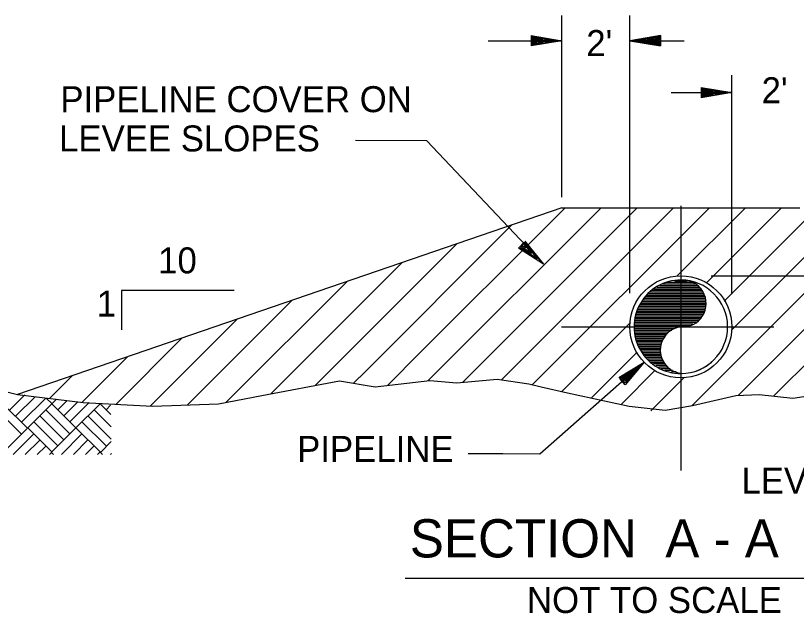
# Model space of a CAD drawing. Extents: x 2127959 to 2137375, y 2146193 to 2153470.
# Drawn here: x 2129309 to 2130299, y 2148422 to 2149179 of the extents above; entities that cross this region are included whole.
import ezdxf

# ---------------------------------------------------------------- set-up
doc = ezdxf.new("R2010")
doc.units = 0
for name, color, linetype in [('Level 1', 7, 'Continuous'), ('Level 3', 7, 'Continuous'), ('Level 5', 7, 'Continuous'), ('Level 50', 7, 'Continuous'), ('Level 63', 7, 'Continuous')]:
    doc.layers.add(name, color=color, linetype=linetype)

msp = doc.modelspace()

# ---------------------------------------------------------------- linework, layer by layer
at = {"layer": 'Level 1'}
for p, q in [((2129830.608, 2149020.936), (2129739.923, 2149021.327)), ((2129830.608, 2149020.936), (2129978.077, 2148864.503)), ((2130001.469, 2148936.091), (2129311.86, 2148699.457)), ((2130001.469, 2148936.091), (2129311.86, 2148699.457)), ((2130001.469, 2148936.091), (2129311.86, 2148699.457)), ((2130001.469, 2148936.091), (2130303.174, 2148936.091))]:
    msp.add_line(p, q, dxfattribs=at)
at = {"layer": 'Level 3'}
for p, q in [((2130001.469, 2148949.346), (2130001.469, 2149179.416)), ((2130087.67, 2148827.839), (2130087.67, 2149179.416)), ((2129908.122, 2149147.68), (2130001.469, 2149147.68)), ((2129962.715, 2149154.144), (2129962.715, 2149141.23)), ((2129962.715, 2149154.144), (2130001.469, 2149147.68)), ((2130001.469, 2149147.68), (2129962.715, 2149147.68)), ((2130001.469, 2149147.68), (2129962.715, 2149141.23)), ((2129963.277, 2149142.023), (2129995.687, 2149147.215)), ((2129963.449, 2149147.041), (2129963.277, 2149142.023)), ((2129963.484, 2149153.006), (2129963.424, 2149148.23)), ((2129963.424, 2149148.23), (2129995.739, 2149148.089)), ((2129964.239, 2149147.057), (2129964.231, 2149142.919)), ((2129964.231, 2149142.919), (2129988.269, 2149146.523)), ((2129995.687, 2149147.215), (2129964.239, 2149147.057)), ((2129964.298, 2149153.074), (2129964.282, 2149148.816)), ((2129964.282, 2149148.816), (2129988.487, 2149148.642)), ((2129995.739, 2149148.089), (2129964.298, 2149153.074)), ((2129988.269, 2149146.523), (2129965.053, 2149146.197)), ((2129965.053, 2149146.197), (2129965.127, 2149143.816)), ((2129965.127, 2149143.816), (2129977.802, 2149145.525)), ((2129988.487, 2149148.642), (2129965.141, 2149152.108)), ((2129965.141, 2149152.108), (2129965.141, 2149149.731)), ((2129965.141, 2149149.731), (2129977.627, 2149149.523)), ((2129977.802, 2149145.525), (2129966.028, 2149145.576)), ((2129966.028, 2149145.576), (2129966.043, 2149144.606)), ((2129977.627, 2149149.523), (2129966.07, 2149151.368)), ((2129966.07, 2149151.368), (2129966.096, 2149150.42)), ((2129966.096, 2149150.42), (2129969.76, 2149150.316)), ((2130126.42, 2149154.144), (2130087.67, 2149147.68)), ((2130087.67, 2149147.68), (2130156.332, 2149147.68)), ((2130087.67, 2149147.68), (2130126.42, 2149147.68)), ((2130087.67, 2149147.68), (2130126.42, 2149141.23)), ((2130125.617, 2149153.366), (2130094.223, 2149148.126)), ((2130094.223, 2149148.126), (2130125.008, 2149148.489)), ((2130125.792, 2149142.089), (2130094.32, 2149147.075)), ((2130094.32, 2149147.075), (2130124.949, 2149147.075)), ((2130124.949, 2149152.561), (2130100.454, 2149148.627)), ((2130100.454, 2149148.627), (2130124.084, 2149149.245)), ((2130125.045, 2149142.886), (2130100.607, 2149146.592)), ((2130100.607, 2149146.592), (2130124.181, 2149146.35)), ((2130124.012, 2149151.595), (2130109.712, 2149149.454)), ((2130109.712, 2149149.454), (2130123.298, 2149149.678)), ((2130124.161, 2149143.8), (2130109.897, 2149145.854)), ((2130109.897, 2149145.854), (2130123.397, 2149145.628)), ((2130123.355, 2149150.851), (2130119.26, 2149150.231)), ((2130123.298, 2149149.678), (2130123.355, 2149150.851)), ((2130123.397, 2149145.628), (2130123.571, 2149144.49)), ((2130124.084, 2149149.245), (2130124.012, 2149151.595)), ((2130124.181, 2149146.35), (2130124.161, 2149143.8)), ((2130125.008, 2149148.489), (2130124.949, 2149152.561)), ((2130124.949, 2149147.075), (2130125.045, 2149142.886)), ((2130125.68, 2149148.593), (2130125.617, 2149153.366)), ((2130125.728, 2149147.057), (2130125.792, 2149142.089)), ((2130126.42, 2149154.144), (2130126.42, 2149141.23)), ((2129966.043, 2149144.606), (2129969.63, 2149144.904)), ((2130123.571, 2149144.49), (2130119.245, 2149145.073)), ((2130216.974, 2148826.713), (2130216.974, 2149104.163)), ((2130178.219, 2149088.339), (2130178.219, 2149075.426)), ((2130178.219, 2149088.339), (2130216.974, 2149081.872)), ((2130178.985, 2149087.2), (2130178.927, 2149082.424)), ((2130179.803, 2149087.268), (2130179.784, 2149083.012)), ((2130211.241, 2149082.285), (2130179.803, 2149087.268)), ((2130203.988, 2149082.84), (2130180.645, 2149086.304)), ((2130180.645, 2149086.304), (2130180.645, 2149083.926)), ((2130139.865, 2149081.872), (2130216.974, 2149081.872)), ((2130216.974, 2149081.872), (2130178.219, 2149081.872)), ((2130216.974, 2149081.872), (2130178.219, 2149075.426)), ((2130178.783, 2149076.218), (2130211.189, 2149081.407)), ((2130178.952, 2149081.236), (2130178.783, 2149076.218)), ((2130178.927, 2149082.424), (2130211.241, 2149082.285)), ((2130179.741, 2149081.249), (2130179.731, 2149077.113)), ((2130179.731, 2149077.113), (2130203.773, 2149080.715)), ((2130211.189, 2149081.407), (2130179.741, 2149081.249)), ((2130179.784, 2149083.012), (2130203.988, 2149082.84)), ((2130203.773, 2149080.715), (2130180.556, 2149080.389)), ((2130180.556, 2149080.389), (2130180.63, 2149078.01)), ((2130180.63, 2149078.01), (2130193.304, 2149079.717)), ((2130180.645, 2149083.926), (2130193.128, 2149083.718)), ((2130193.304, 2149079.717), (2130181.528, 2149079.768)), ((2130181.528, 2149079.768), (2130181.548, 2149078.806)), ((2130181.548, 2149078.806), (2130185.129, 2149079.097)), ((2130193.128, 2149083.718), (2130181.574, 2149085.561)), ((2130181.574, 2149085.561), (2130181.602, 2149084.614)), ((2130181.602, 2149084.614), (2130185.264, 2149084.511)), ((2130152.32, 2148938.452), (2130152.32, 2148603.239)), ((2130190.765, 2148849.885), (2130836.581, 2148849.885)), ((2130190.765, 2148849.885), (2130836.581, 2148849.885)), ((2130190.765, 2148849.885), (2130836.581, 2148849.885)), ((2130170.464, 2148839.161), (2130129.065, 2148839.161)), ((2130167.662, 2148841.178), (2130133.054, 2148841.178)), ((2130160.279, 2148843.198), (2130144.8, 2148843.198)), ((2129443.731, 2148831.229), (2129443.731, 2148781.284)), ((2129586.223, 2148831.229), (2129443.731, 2148831.229)), ((2130179.993, 2148829.057), (2130113.055, 2148829.057)), ((2130178.761, 2148831.075), (2130114.821, 2148831.075)), ((2130177.534, 2148833.097), (2130118.277, 2148833.097)), ((2130176.062, 2148835.12), (2130121.872, 2148835.12)), ((2130173.263, 2148837.14), (2130125.472, 2148837.14)), ((2130183.467, 2148818.955), (2130104.241, 2148818.955)), ((2130183.171, 2148820.976), (2130106.003, 2148820.976)), ((2130182.873, 2148822.995), (2130107.768, 2148822.995)), ((2130182.446, 2148825.016), (2130109.531, 2148825.016)), ((2130181.215, 2148827.035), (2130111.298, 2148827.035)), ((2130183.749, 2148810.876), (2130099.656, 2148810.872)), ((2130184.273, 2148812.897), (2130100.449, 2148812.897)), ((2130184.06, 2148814.914), (2130101.25, 2148814.914)), ((2130183.763, 2148816.934), (2130102.478, 2148816.934)), ((2130180.646, 2148800.773), (2130095.664, 2148800.773)), ((2130181.651, 2148802.794), (2130096.467, 2148802.794)), ((2130182.176, 2148804.814), (2130097.261, 2148804.814)), ((2130182.701, 2148806.835), (2130098.06, 2148806.835)), ((2130183.227, 2148808.853), (2130098.855, 2148808.853)), ((2130171.188, 2148790.672), (2130094.078, 2148790.672)), ((2130174.449, 2148792.69), (2130094.147, 2148792.688)), ((2130176, 2148794.711), (2130094.218, 2148794.711)), ((2130177.55, 2148796.734), (2130094.285, 2148796.734)), ((2130179.097, 2148798.752), (2130094.869, 2148798.752)), ((2130001.009, 2148785.236), (2130270.124, 2148785.236)), ((2130140.696, 2148780.569), (2130093.73, 2148780.569)), ((2130144.39, 2148782.587), (2130093.798, 2148782.587)), ((2130149.676, 2148784.609), (2130093.868, 2148784.609)), ((2130164.079, 2148786.631), (2130093.938, 2148786.631)), ((2130167.63, 2148788.651), (2130094.011, 2148788.651)), ((2130137.009, 2148778.549), (2130093.662, 2148778.549)), ((2130137.009, 2148778.549), (2130093.662, 2148778.549)), ((2130135.267, 2148776.529), (2130093.808, 2148776.529)), ((2130133.669, 2148774.511), (2130094.448, 2148774.511)), ((2130132.068, 2148772.49), (2130095.088, 2148772.49)), ((2130130.47, 2148770.471), (2130095.73, 2148770.471)), ((2130129.219, 2148768.447), (2130096.371, 2148768.447)), ((2130128.665, 2148766.428), (2130097.009, 2148766.428)), ((2130128.101, 2148764.404), (2130097.654, 2148764.404)), ((2130127.542, 2148762.387), (2130098.297, 2148762.387)), ((2130126.983, 2148760.366), (2130098.931, 2148760.366)), ((2130126.423, 2148758.348), (2130099.576, 2148758.348)), ((2130126.466, 2148756.326), (2130100.945, 2148756.326)), ((2130126.729, 2148754.305), (2130102.476, 2148754.305)), ((2130126.995, 2148752.285), (2130104.011, 2148752.285)), ((2130127.259, 2148750.263), (2130105.542, 2148750.263)), ((2130127.259, 2148750.263), (2130105.542, 2148750.263)), ((2130127.522, 2148748.244), (2130107.073, 2148748.245)), ((2130127.787, 2148746.223), (2130108.602, 2148746.223)), ((2130128.903, 2148744.203), (2130110.134, 2148744.203)), ((2130130.085, 2148742.186), (2130111.666, 2148742.186)), ((2130131.271, 2148740.163), (2130114.551, 2148740.163)), ((2130132.454, 2148738.145), (2130117.631, 2148738.145)), ((2130133.64, 2148736.124), (2130120.709, 2148736.124)), ((2130136.162, 2148734.1), (2130123.787, 2148734.1)), ((2130138.874, 2148732.084), (2130126.87, 2148732.084)), ((2130141.579, 2148730.06), (2130132.068, 2148730.06)), ((2130146.466, 2148728.04), (2130140.36, 2148728.04)), ((2130146.466, 2148728.04), (2130140.36, 2148728.04))]:
    msp.add_line(p, q, dxfattribs=at)
msp.add_lwpolyline([(2130105.729, 2148740.417), (2129973.646, 2148623.943), (2129926.672, 2148624.261), (2129882.878, 2148624.261)], dxfattribs=at)
msp.add_circle((2130152.321, 2148785.236), 64.651, dxfattribs=at)
for centre, radius, start, end in [((2130152.321, 2148785.236), 59.263, 89.972239, 270.065958), ((2130154.781, 2148814.702), 29.592, 265.228306, 93.676883), ((2130152.321, 2148785.236), 59.263, 270.065994, 89.972197), ((2130155.9, 2148755.7), 29.704, 96.821831, 267.669103), ((2130152.32, 2148785.238), 59.265, 270.001317, 317.112911)]:
    msp.add_arc(centre, radius, start, end, dxfattribs=at)
at = {"layer": 'Level 5'}
for p, q in [((2129801.831, 2148732.275), (2130005.64, 2148936.091)), ((2129832.32, 2148717.053), (2130051.356, 2148936.091)), ((2129875.769, 2148714.785), (2130097.071, 2148936.091)), ((2129924.935, 2148718.238), (2130142.782, 2148936.091)), ((2129964.13, 2148711.715), (2130188.501, 2148936.091)), ((2130147.792, 2148849.664), (2130234.214, 2148936.091)), ((2130184.514, 2148840.671), (2130279.93, 2148936.091)), ((2130207.28, 2148817.725), (2130319.902, 2148930.349)), ((2130216.843, 2148781.571), (2130353.941, 2148918.659)), ((2129745.443, 2148721.603), (2129938.221, 2148914.384)), ((2130166.072, 2148685.086), (2130387.975, 2148906.991)), ((2129689.057, 2148710.932), (2129868.63, 2148890.507)), ((2130225.007, 2148698.303), (2130422.013, 2148895.308)), ((2130270, 2148697.582), (2130456.049, 2148883.631)), ((2129632.671, 2148700.264), (2129799.032, 2148866.628)), ((2129576.284, 2148689.591), (2129729.434, 2148842.746)), ((2129527.382, 2148686.403), (2129659.839, 2148818.859)), ((2129480.285, 2148685.024), (2129590.244, 2148794.98)), ((2130001.418, 2148703.291), (2130088.682, 2148790.553)), ((2129436.685, 2148687.14), (2129520.645, 2148771.097)), ((2130038.949, 2148695.106), (2130096.919, 2148753.074)), ((2129393.228, 2148689.393), (2129451.05, 2148747.218)), ((2129780.594, 2148711.04), (2129801.625, 2148732.071)), ((2130076.54, 2148686.982), (2130119.681, 2148730.125)), ((2129352.545, 2148694.427), (2129381.455, 2148723.338)), ((2129737.527, 2148713.689), (2129745.301, 2148721.465)), ((2130114.13, 2148678.858), (2130156.822, 2148721.55)), ((2129256.196, 2148713.472), (2129311.86, 2148699.457)), ((2129621.533, 2148698.156), (2129719.629, 2148716.63)), ((2129719.629, 2148716.63), (2129764.825, 2148709.209)), ((2129764.825, 2148709.209), (2129834.102, 2148717.26)), ((2129834.102, 2148717.26), (2129868.641, 2148714.103)), ((2129868.641, 2148714.103), (2129919.763, 2148718.998)), ((2129919.763, 2148718.998), (2129959.628, 2148713.154)), ((2129959.628, 2148713.154), (2129975.225, 2148709.209)), ((2129975.225, 2148709.209), (2130008.78, 2148701.63)), ((2130008.78, 2148701.63), (2130086.936, 2148684.732)), ((2130294.175, 2148694.997), (2130348.058, 2148702.737)), ((2129302.25, 2148679.982), (2129321.236, 2148698.97)), ((2129309.884, 2148672.398), (2129334.186, 2148696.696)), ((2129311.86, 2148699.457), (2129395.148, 2148689.156)), ((2129347.779, 2148695.016), (2129317.499, 2148664.734)), ((2129348.287, 2148694.951), (2129355.6, 2148687.633)), ((2129355.468, 2148687.759), (2129361.082, 2148693.369)), ((2129363.07, 2148680.159), (2129374.608, 2148691.697)), ((2129566.464, 2148687.733), (2129621.533, 2148698.156)), ((2130167.267, 2148685.369), (2130221.936, 2148698.156)), ((2130221.936, 2148698.156), (2130251.347, 2148699.576)), ((2130251.347, 2148699.576), (2130294.175, 2148694.997)), ((2129293.99, 2148686.968), (2129324.34, 2148656.617)), ((2129324.993, 2148657.28), (2129355.472, 2148687.764)), ((2129385.945, 2148657.28), (2129355.468, 2148687.759)), ((2129388.351, 2148690.16), (2129370.71, 2148672.518)), ((2129402.644, 2148689.233), (2129378.322, 2148664.906)), ((2129385.945, 2148657.28), (2129416.422, 2148687.759)), ((2129395.148, 2148689.156), (2129482.978, 2148684.892)), ((2129416.422, 2148687.759), (2129430.029, 2148674.146)), ((2129424.054, 2148680.127), (2129429.792, 2148685.865)), ((2129482.978, 2148684.892), (2129566.464, 2148687.733)), ((2130086.936, 2148684.732), (2130132.33, 2148679.683)), ((2130132.33, 2148679.683), (2130167.267, 2148685.369)), ((2129286.39, 2148679.363), (2129316.738, 2148649.019)), ((2129340.229, 2148672.518), (2129370.71, 2148642.039)), ((2129347.818, 2148680.159), (2129378.323, 2148649.656)), ((2129430.666, 2148643.033), (2129401.18, 2148672.518)), ((2129408.821, 2148680.159), (2129430.349, 2148658.632)), ((2129363.07, 2148634.403), (2129332.569, 2148664.906)), ((2129424.072, 2148634.403), (2129393.57, 2148664.906)), ((2129293.858, 2148626.135), (2129324.331, 2148656.613)), ((2129355.468, 2148626.805), (2129324.993, 2148657.28)), ((2129355.468, 2148626.755), (2129385.945, 2148657.231)), ((2129385.945, 2148657.28), (2129416.422, 2148626.805)), ((2129306.513, 2148623.59), (2129331.958, 2148649.036)), ((2129339.572, 2148641.374), (2129321.785, 2148623.589)), ((2129367.496, 2148623.579), (2129393.57, 2148649.656)), ((2129401.18, 2148641.993), (2129382.768, 2148623.578)), ((2129347.209, 2148633.785), (2129337.008, 2148623.586)), ((2129408.821, 2148634.403), (2129397.987, 2148623.575)), ((2129417.08, 2148626.155), (2129430.732, 2148639.808)), ((2129352.257, 2148623.583), (2129354.814, 2148626.135)), ((2129357.418, 2148623.581), (2129354.857, 2148626.135)), ((2129413.24, 2148623.573), (2129416.422, 2148626.755)), ((2129417.03, 2148626.155), (2129419.618, 2148623.573)), ((2129429.699, 2148623.568), (2129431.038, 2148624.907))]:
    msp.add_line(p, q, dxfattribs=at)
at = {"layer": 'Level 50'}
for p, q in [((2129970.454, 2148871.411), (2129970.454, 2148871.411)), ((2129978.077, 2148864.503), (2129978.077, 2148864.503)), ((2130105.766, 2148740.386), (2130105.766, 2148740.386)), ((2130097.95, 2148733.683), (2130097.95, 2148733.683))]:
    msp.add_line(p, q, dxfattribs=at)
for points in [[(2129954.778, 2148893.877), (2129978.077, 2148864.503), (2129946.563, 2148884.766), (2129953.591, 2148892.549), (2129970.454, 2148871.411), (2129949.066, 2148885.18), (2129953.576, 2148890.174), (2129963.142, 2148878.056), (2129951.546, 2148885.582), (2129953.418, 2148887.64), (2129955.504, 2148884.945)], [(2130073.692, 2148720.961), (2130105.766, 2148740.386), (2130081.675, 2148711.664), (2130074.872, 2148719.618), (2130097.95, 2148733.683), (2130081.586, 2148714.209), (2130077.201, 2148719.295), (2130090.439, 2148727.245), (2130081.52, 2148716.726), (2130079.698, 2148718.829), (2130082.637, 2148720.564)]]:
    msp.add_lwpolyline(points, dxfattribs=at)
at = {"layer": 'Level 63'}
msp.add_line((2129803.161, 2148466.947), (2130438.856, 2148466.947), dxfattribs=at)

# ---------------------------------------------------------------- texts
at = {"layer": 'Level 1'}
for s, p in [("2'", (2130032.503, 2149128.196)), ("2'", (2130254.632, 2149068.417)), ('PIPELINE COVER ON ', (2129366.127, 2149057.11)), ('LEVEE SLOPES', (2129364.55, 2149007.338)), ('10', (2129490.081, 2148852.894)), ('1', (2129412.317, 2148798.104)), ('PIPELINE', (2129666.138, 2148613.998)), ('LEVEE SURFACE', (2130229.033, 2148573.84)), ('NOT TO SCALE', (2129957.323, 2148422.673))]:
    msp.add_text(s, height=32.931, dxfattribs=at).set_placement(p)
at = {"layer": 'Level 63'}
msp.add_text('SECTION  A - A', height=48.4, dxfattribs=at).set_placement((2129808.953, 2148493.071))

doc.saveas('drawing.dxf')
